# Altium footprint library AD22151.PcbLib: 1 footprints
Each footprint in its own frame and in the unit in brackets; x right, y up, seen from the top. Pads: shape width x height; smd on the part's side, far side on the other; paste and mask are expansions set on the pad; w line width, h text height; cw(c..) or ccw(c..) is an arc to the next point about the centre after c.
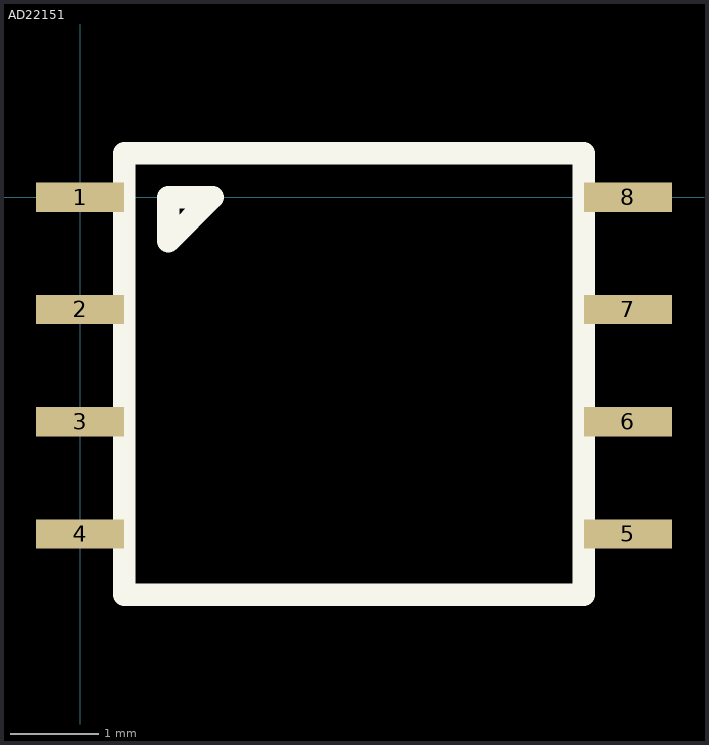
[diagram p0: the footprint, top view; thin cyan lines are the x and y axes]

## AD22151 [mm] "Magnetic Sensor"
pads (8):
  rect 1x0.33 smd: 1(0,0) 2(0,-1.27) 3(0,-2.54) 4(0,-3.81) 5(6.2,-3.81) 6(6.2,-2.54) 7(6.2,-1.27) 8(6.2,0)
Top Overlay:
  lines w0.254: 0.5,-4.5 5.7,-4.5 5.7,0.5 0.5,0.5 0.5,-4.5 ; 1,-0.5 1.5,0 1,0 1,-0.5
